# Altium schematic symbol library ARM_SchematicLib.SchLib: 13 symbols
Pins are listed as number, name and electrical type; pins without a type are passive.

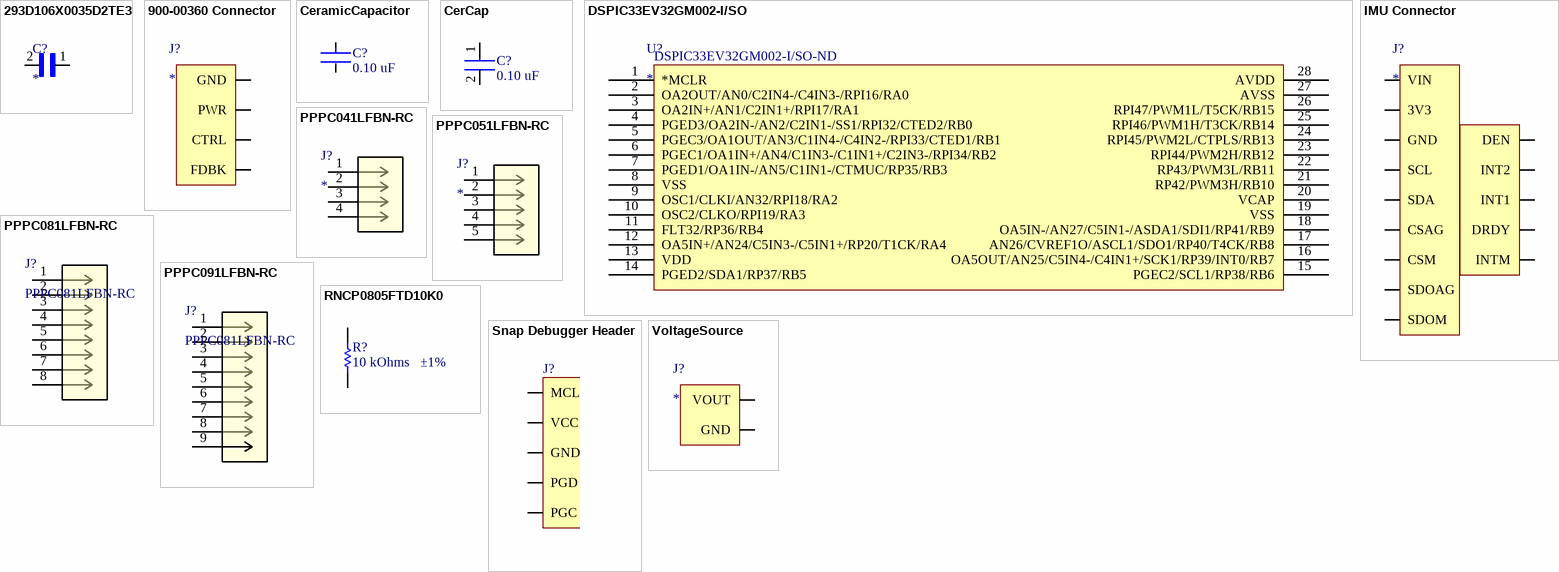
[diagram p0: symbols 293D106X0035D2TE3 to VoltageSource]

## 293D106X0035D2TE3
designator C?
Capacitor: tantalum; 10uF; 35VDC; SMD; Case: D; Â±20%; -55Ã·125Â°C; MF: {'manufacturer': u'Vishay Sprague'}; MP: 293D106X0035D2TE3
footprint CAPPM7343X310N
pins: 1, 2

## 900-00360 Connector
designator J?
SERVOMOTOR Connector
footprint CONN_PPPC041LFBN-RC_SUL
pins: 1 GND, 2 PWR, 3 CTRL, 4 FDBK

## CeramicCapacitor
designator C?, comment 0.10 uF
CAP CER 0.1UF; Manufacturer: KEMET; Manufacturer Part Number: C0603C104K5RACTU; Tolerance: 0.1; Temperature Coefficient: 30ppm/°C; Material: Ceramic; Automotive Grade: Grade 1; Voltage Rating: 50 V; Capacitance: 0.10 μF; Temperature Characteristic: X7R
footprint CAPC17595_95N_KEM
pins: 1, 2

## CerCap
designator C?, comment 0.10 uF
CAP CER 0.1UF; Manufacturer: KEMET; Manufacturer Part Number: C0603C104K5RACTU; Tolerance: 0.1; Temperature Coefficient: 30ppm/°C; Material: Ceramic; Automotive Grade: Grade 1; Voltage Rating: 50 V; Capacitance: 0.10 μF; Temperature Characteristic: X7R
footprint CAPC17595_95N_KEM
pins: 1, 2

## DSPIC33EV32GM002-I/SO
designator U?  Supplier Part Number 1: DSPIC33EV32GM002-I/SO-ND
footprint SOIC127P1030X265-28N
pins: 1 *MCLR, 2 OA2OUT/AN0/C2IN4-/C4IN3-/RPI16/RA0, 3 OA2IN+/AN1/C2IN1+/RPI17/RA1, 4 PGED3/OA2IN-/AN2/C2IN1-/SS1/RPI32/CTED2/RB0, 5 PGEC3/OA1OUT/AN3/C1IN4-/C4IN2-/RPI33/CTED1/RB1, 6 PGEC1/OA1IN+/AN4/C1IN3-/C1IN1+/C2IN3-/RPI34/RB2, 7 PGED1/OA1IN-/AN5/C1IN1-/CTMUC/RP35/RB3, 8 VSS, 9 OSC1/CLKI/AN32/RPI18/RA2, 10 OSC2/CLKO/RPI19/RA3, 11 FLT32/RP36/RB4, 12 OA5IN+/AN24/C5IN3-/C5IN1+/RP20/T1CK/RA4, 13 VDD, 14 PGED2/SDA1/RP37/RB5, 15 PGEC2/SCL1/RP38/RB6, 16 OA5OUT/AN25/C5IN4-/C4IN1+/SCK1/RP39/INT0/RB7, 17 AN26/CVREF1O/ASCL1/SDO1/RP40/T4CK/RB8, 18 OA5IN-/AN27/C5IN1-/ASDA1/SDI1/RP41/RB9, 19 VSS, 20 VCAP, 21 RP42/PWM3H/RB10, 22 RP43/PWM3L/RB11, 23 RPI44/PWM2H/RB12, 24 RPI45/PWM2L/CTPLS/RB13, 25 RPI46/PWM1H/T3CK/RB14, 26 RPI47/PWM1L/T5CK/RB15, 27 AVSS, 28 AVDD

## IMU Connector
designator J?
LSM9DS1 ACCEL/MAG/GYRO/TEMP BRD Connections
footprint IMU Connector
pins: 1 VIN, 2 3V3, 3 GND, 4 SCL, 5 SDA, 6 CSAG, 7 CSM, 8 SDOAG, 9 SDOM, 10 DEN, 11 INT2, 12 INT1, 13 DRDY, 14 INTM

## PPPC041LFBN-RC
designator J?
No Description Available; Mfr_Name: Sullins
footprint CONN_PPPC041LFBN-RC_SUL
pins: 1, 2, 3, 4

## PPPC051LFBN-RC
designator J?
No Description Available; Mfr_Name: Sullins
footprint CONN_PPPC051LFBN-RC_SUL
footprint CONN_PPPC051LFBN-RC_SUL
pins: 1, 2, 3, 4, 5

## PPPC081LFBN-RC
designator J?
No Description Available; Mfr_Name: Sullins
footprint CONN8_LFBN-RC_SUL
pins: 1, 2, 3, 4, 5, 6, 7, 8

## PPPC091LFBN-RC
designator J?, comment PPPC081LFBN-RC
No Description Available; Mfr_Name: Sullins
footprint CONN9_LFBN-RC_SUL
pins: 1, 2, 3, 4, 5, 6, 7, 8, 9

## RNCP0805FTD10K0
designator R?  value 10 kOhms   ±1%  (hidden comment: RNCP0805FTD10K0)
RES 10K OHM 1% 1/4W 0805
footprint RNCP0805FTD10K0_V2 (Footprint not found)
pins: 1, 2

## Snap Debugger Header
designator J?, comment PPPC051LFBN-RC  (value not drawn)
Manufacturer: Sullins; Number of Positions: 5; Connector Type: Header; Pitch: 0.1inch
footprint PPPC051LFBN-RC
footprint CONN_PPPC051LFBN-RC_SUL
pins: 1 MCLR, 2 VCC, 3 GND, 4 PGD, 5 PGC

## VoltageSource
designator J?
footprint CONN2_5-3021_MOL
pins: 1 VOUT, 2 GND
